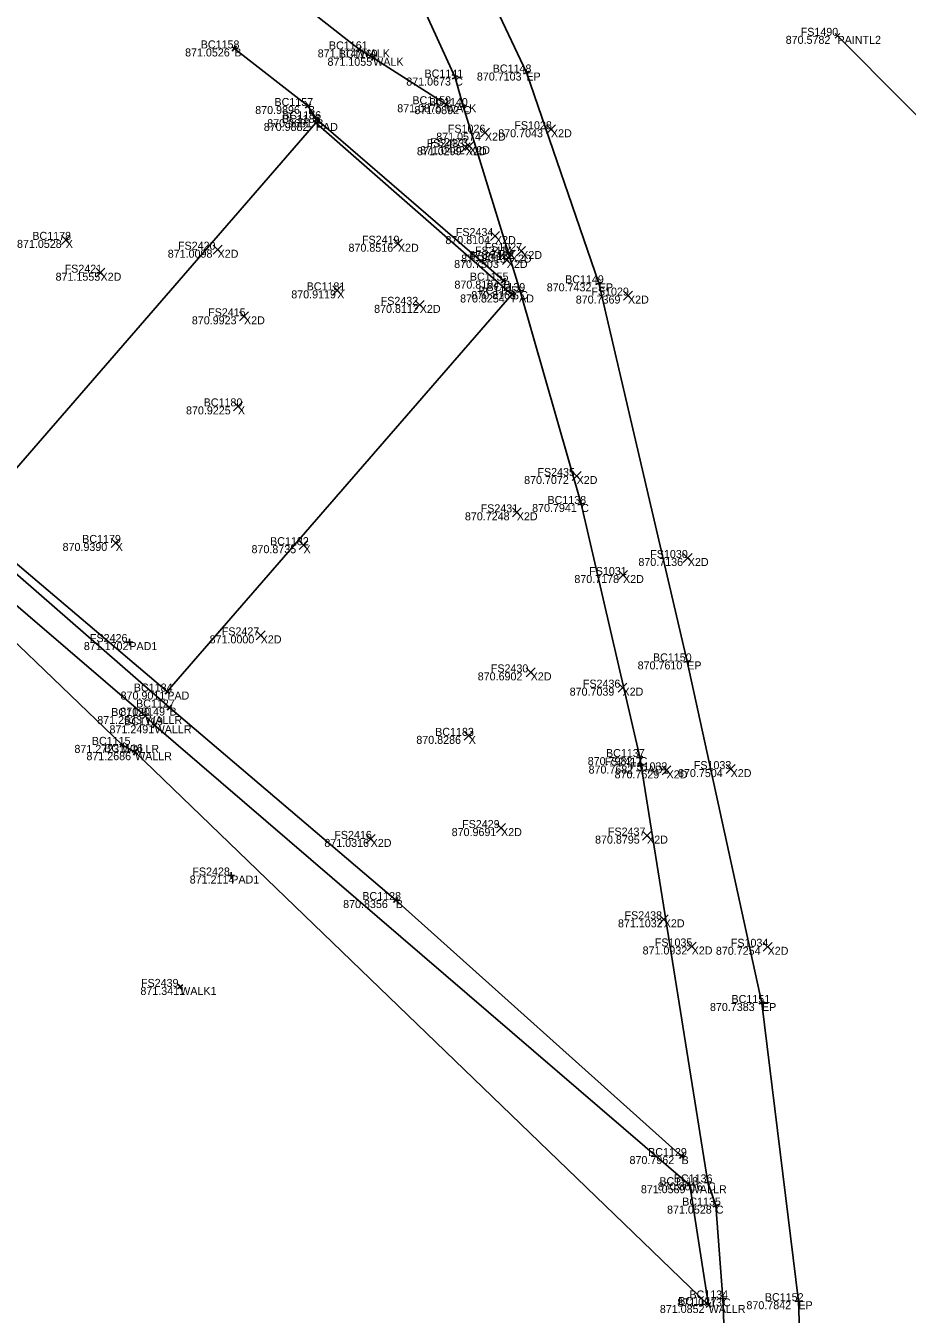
# Model space of a CAD drawing. Extents: x 1479425 to 1480294, y 379351 to 380102.
# Drawn here: x 1479567.93 to 1479574.53, y 379932.66 to 379942.32 of the extents above; entities that cross this region are included whole.
import ezdxf

# ---------------------------------------------------------------- set-up
doc = ezdxf.new("R2010")
doc.units = 0
for name, color, linetype in [('PM_X_Crosswalk', 7, 'Continuous'), ('PV_X_Curb', 7, 'Continuous'), ('PV_X_Walk', 7, 'Continuous'), ('RD_X_Concrete_Pad', 7, 'Continuous'), ('RD_X_Wall', 7, 'Continuous'), ('SV_X_Break_Lines', 7, 'Continuous'), ('SV_X_Random_Point', 7, 'Continuous'), ('SV_X_Shot_Marker', 7, 'Continuous'), ('SV_X_Text_Comment', 7, 'Continuous'), ('SV_X_Text_Elevation', 7, 'Continuous'), ('SV_X_Text_Name', 7, 'Continuous')]:
    doc.layers.add(name, color=color, linetype=linetype)

msp = doc.modelspace()

# ---------------------------------------------------------------- linework, layer by layer
at = {"layer": 'PM_X_Crosswalk'}
msp.add_lwpolyline([(1479636.371, 379879.5548), (1479574.01, 379942.241)], dxfattribs=at)
at = {"layer": 'PV_X_Curb'}
for points in [[(1479569.7374, 379946.0713), (1479571.6786, 379941.966), (1479572.2211, 379940.3862), (1479572.8837, 379937.5528), (1479573.4441, 379934.9926), (1479573.7165, 379932.7579), (1479573.8423, 379929.1036), (1479573.6746, 379925.8552), (1479573.045, 379921.8877), (1479571.771, 379917.2335), (1479569.497, 379912.1606), (1479567.166, 379908.6426), (1479563.944, 379905.002), (1479559.953, 379901.7586), (1479555.611, 379898.8117), (1479545.712, 379894.1043)], [(1479569.6747, 379945.147), (1479571.1449, 379941.9283), (1479571.2063, 379941.7143), (1479571.6328, 379940.3278), (1479572.0894, 379938.7326), (1479572.5276, 379936.8356), (1479573.0389, 379933.6479), (1479573.0983, 379933.4742), (1479573.1518, 379932.7783), (1479573.1584, 379932.5909), (1479573.2592, 379931.0122), (1479573.2781, 379927.5231), (1479573.155, 379925.8406), (1479572.586, 379922.1301), (1479571.403, 379917.5039), (1479569.157, 379912.5107), (1479566.948, 379909.0554), (1479563.851, 379905.5223), (1479559.694, 379902.1479), (1479555.354, 379899.3068), (1479545.42, 379894.5976)]]:
    msp.add_lwpolyline(points, dxfattribs=at)
at = {"layer": 'PV_X_Walk'}
msp.add_lwpolyline([(1479571.0763, 379941.7282), (1479570.531, 379942.0765), (1479570.4288, 379942.1393), (1479568.9868, 379943.271), (1479567.7208, 379944.1895), (1479567.6443, 379944.2666), (1479565.7789, 379946.1858), (1479564.4031, 379947.7838), (1479564.3033, 379947.845), (1479562.7309, 379949.5948), (1479560.4775, 379951.9792)], dxfattribs=at)
at = {"layer": 'RD_X_Concrete_Pad'}
msp.add_lwpolyline([(1479568.9885, 379937.3268), (1479571.5704, 379940.3025), (1479570.1014, 379941.5882), (1479567.4997, 379938.5893)], close=True, dxfattribs=at)
at = {"layer": 'RD_X_Wall'}
msp.add_lwpolyline([(1479564.6337, 379940.7266), (1479567.168, 379938.3359), (1479567.2924, 379938.2311), (1479568.6502, 379936.9271), (1479568.7466, 379936.8724), (1479573.0444, 379932.7293), (1479572.9032, 379933.627), (1479568.8936, 379937.0738), (1479568.8238, 379937.1435), (1479567.359, 379938.3988), (1479567.2981, 379938.4814), (1479564.6647, 379940.8093)], dxfattribs=at)
at = {"layer": 'SV_X_Break_Lines'}
for points in [[(1479571.5063, 379940.4064), (1479570.1057, 379941.6162), (1479570.0424, 379941.7153), (1479569.4905, 379942.1465)], [(1479564.6308, 379940.8576), (1479566.1289, 379939.6067), (1479567.3964, 379938.6081), (1479569.0046, 379937.2067), (1479570.7003, 379935.7642), (1479572.8418, 379933.8454)]]:
    msp.add_lwpolyline(points, dxfattribs=at)
at = {"layer": 'SV_X_Random_Point'}
for p, q in [((1479571.3347, 379941.482), (1479571.4013, 379941.5488)), ((1479571.3347, 379941.5488), (1479571.4013, 379941.482)), ((1479571.8297, 379941.5075), (1479571.8963, 379941.5743)), ((1479571.8297, 379941.5743), (1479571.8963, 379941.5075)), ((1479571.1917, 379941.3729), (1479571.2583, 379941.4397)), ((1479571.1917, 379941.4397), (1479571.2583, 379941.3729)), ((1479571.2167, 379941.3805), (1479571.2833, 379941.4473)), ((1479571.2167, 379941.4473), (1479571.2833, 379941.3805)), ((1479568.1945, 379940.6784), (1479568.2611, 379940.7452)), ((1479568.1945, 379940.7452), (1479568.2611, 379940.6784)), ((1479571.4097, 379940.7069), (1479571.4763, 379940.7737)), ((1479571.4097, 379940.7737), (1479571.4763, 379940.7069)), ((1479569.3317, 379940.6047), (1479569.3983, 379940.6715)), ((1479569.3317, 379940.6715), (1479569.3983, 379940.6047)), ((1479570.6827, 379940.6495), (1479570.7493, 379940.7163)), ((1479570.6827, 379940.7163), (1479570.7493, 379940.6495)), ((1479571.6067, 379940.5949), (1479571.6733, 379940.6617)), ((1479571.6067, 379940.6617), (1479571.6733, 379940.5949)), ((1479571.4987, 379940.5276), (1479571.5653, 379940.5944)), ((1479571.4987, 379940.5944), (1479571.5653, 379940.5276)), ((1479571.5287, 379940.568), (1479571.5953, 379940.6348)), ((1479571.5287, 379940.6348), (1479571.5953, 379940.568)), ((1479568.4547, 379940.4323), (1479568.5213, 379940.4991)), ((1479568.4547, 379940.4991), (1479568.5213, 379940.4323)), ((1479570.2279, 379940.3), (1479570.2945, 379940.3668)), ((1479570.2279, 379940.3668), (1479570.2945, 379940.3)), ((1479570.8467, 379940.1914), (1479570.9133, 379940.2582)), ((1479570.8467, 379940.2582), (1479570.9133, 379940.1914)), ((1479572.4067, 379940.2609), (1479572.4733, 379940.3277)), ((1479572.4067, 379940.3277), (1479572.4733, 379940.2609)), ((1479569.5297, 379940.1056), (1479569.5963, 379940.1724)), ((1479569.5297, 379940.1724), (1479569.5963, 379940.1056)), ((1479569.4841, 379939.4305), (1479569.5507, 379939.4973)), ((1479569.4841, 379939.4973), (1479569.5507, 379939.4305)), ((1479572.0217, 379938.9087), (1479572.0883, 379938.9755)), ((1479572.0217, 379938.9755), (1479572.0883, 379938.9087)), ((1479571.5737, 379938.6365), (1479571.6403, 379938.7033)), ((1479571.5737, 379938.7033), (1479571.6403, 379938.6365)), ((1479568.5682, 379938.4071), (1479568.6348, 379938.4739)), ((1479568.5682, 379938.4739), (1479568.6348, 379938.4071)), ((1479569.9758, 379938.3903), (1479570.0424, 379938.4571)), ((1479569.9758, 379938.4571), (1479570.0424, 379938.3903)), ((1479572.8547, 379938.2943), (1479572.9213, 379938.3611)), ((1479572.8547, 379938.3611), (1479572.9213, 379938.2943)), ((1479572.3697, 379938.1667), (1479572.4363, 379938.2335)), ((1479572.3697, 379938.2335), (1479572.4363, 379938.1667)), ((1479569.6547, 379937.7144), (1479569.7213, 379937.7812)), ((1479569.6547, 379937.7812), (1479569.7213, 379937.7144)), ((1479571.6777, 379937.437), (1479571.7443, 379937.5038)), ((1479571.6777, 379937.5038), (1479571.7443, 379937.437)), ((1479572.3657, 379937.3227), (1479572.4323, 379937.3895)), ((1479572.3657, 379937.3895), (1479572.4323, 379937.3227)), ((1479571.2134, 379936.9613), (1479571.28, 379937.0281)), ((1479571.2134, 379937.0281), (1479571.28, 379936.9613)), ((1479572.6957, 379936.7027), (1479572.7623, 379936.7695)), ((1479572.6957, 379936.7695), (1479572.7623, 379936.7027)), ((1479573.1757, 379936.7122), (1479573.2423, 379936.779)), ((1479573.1757, 379936.779), (1479573.2423, 379936.7122)), ((1479571.4557, 379936.2702), (1479571.5223, 379936.337)), ((1479571.4557, 379936.337), (1479571.5223, 379936.2702)), ((1479570.4787, 379936.189), (1479570.5453, 379936.2558)), ((1479570.4787, 379936.2558), (1479570.5453, 379936.189)), ((1479572.5497, 379936.2138), (1479572.6163, 379936.2806)), ((1479572.5497, 379936.2806), (1479572.6163, 379936.2138)), ((1479572.6747, 379935.5865), (1479572.7413, 379935.6533)), ((1479572.6747, 379935.6533), (1479572.7413, 379935.5865)), ((1479572.8837, 379935.383), (1479572.9503, 379935.4498)), ((1479572.8837, 379935.4498), (1479572.9503, 379935.383)), ((1479573.4527, 379935.3804), (1479573.5193, 379935.4472)), ((1479573.4527, 379935.4472), (1479573.5193, 379935.3804))]:
    msp.add_line(p, q, dxfattribs=at)
at = {"layer": 'SV_X_Shot_Marker'}
for p, q in [((1479573.9923, 379942.2234), (1479574.0277, 379942.2587)), ((1479574.0276, 379942.2233), (1479573.9924, 379942.2587)), ((1479574.01, 379942.241), (1479574.01, 379942.241)), ((1479569.5102, 379942.1311), (1479569.4708, 379942.1619)), ((1479569.4751, 379942.1268), (1479569.5059, 379942.1662)), ((1479569.4905, 379942.1465), (1479569.4905, 379942.1465)), ((1479570.4501, 379942.1262), (1479570.4075, 379942.1524)), ((1479570.4157, 379942.118), (1479570.4419, 379942.1606)), ((1479570.4288, 379942.1393), (1479570.4288, 379942.1393)), ((1479570.5175, 379942.0555), (1479570.5445, 379942.0976)), ((1479570.5521, 379942.0631), (1479570.5099, 379942.09)), ((1479570.531, 379942.0765), (1479570.531, 379942.0765)), ((1479571.1676, 379941.9387), (1479571.1222, 379941.9179)), ((1479571.1345, 379941.9511), (1479571.1553, 379941.9056)), ((1479571.1449, 379941.9283), (1479571.1449, 379941.9283)), ((1479571.7012, 379941.9767), (1479571.656, 379941.9553)), ((1479571.6679, 379941.9886), (1479571.6893, 379941.9434)), ((1479571.6786, 379941.966), (1479571.6786, 379941.966)), ((1479570.0213, 379941.7019), (1479570.0635, 379941.7288)), ((1479570.0559, 379941.6943), (1479570.0289, 379941.7364)), ((1479570.0424, 379941.7153), (1479570.0424, 379941.7153)), ((1479571.0974, 379941.7148), (1479571.0552, 379941.7417)), ((1479571.0628, 379941.7072), (1479571.0898, 379941.7493)), ((1479571.0763, 379941.7282), (1479571.0763, 379941.7282)), ((1479571.2303, 379941.7212), (1479571.1823, 379941.7074)), ((1479571.1994, 379941.7383), (1479571.2132, 379941.6903)), ((1479571.2063, 379941.7143), (1479571.2063, 379941.7143)), ((1479570.1246, 379941.5999), (1479570.0868, 379941.6326)), ((1479570.0894, 379941.5973), (1479570.122, 379941.6351)), ((1479570.1057, 379941.6162), (1479570.1057, 379941.6162)), ((1479570.1202, 379941.5718), (1479570.0826, 379941.6047)), ((1479570.0849, 379941.5694), (1479570.1179, 379941.607)), ((1479570.1014, 379941.5882), (1479570.1014, 379941.5882)), ((1479571.5252, 379940.3901), (1479571.4874, 379940.4228)), ((1479571.49, 379940.3875), (1479571.5226, 379940.4253)), ((1479571.5063, 379940.4064), (1479571.5063, 379940.4064)), ((1479572.2447, 379940.3943), (1479572.1975, 379940.3781)), ((1479572.213, 379940.4099), (1479572.2292, 379940.3626)), ((1479572.2211, 379940.3862), (1479572.2211, 379940.3862)), ((1479571.5515, 379940.3189), (1479571.5893, 379940.2861)), ((1479571.554, 379940.2836), (1479571.5868, 379940.3214)), ((1479571.5704, 379940.3025), (1479571.5704, 379940.3025)), ((1479571.6567, 379940.3352), (1479571.6089, 379940.3205)), ((1479571.6254, 379940.3517), (1479571.6401, 379940.3039)), ((1479571.6328, 379940.3278), (1479571.6328, 379940.3278)), ((1479572.1134, 379938.7395), (1479572.0654, 379938.7257)), ((1479572.0825, 379938.7567), (1479572.0963, 379938.7086)), ((1479572.0894, 379938.7326), (1479572.0894, 379938.7326)), ((1479568.679, 379937.6976), (1479568.729, 379937.6976)), ((1479568.704, 379937.7226), (1479568.704, 379937.6726)), ((1479568.704, 379937.6976), (1479568.704, 379937.6976)), ((1479572.908, 379937.5585), (1479572.8594, 379937.5471)), ((1479572.878, 379937.5772), (1479572.8894, 379937.5285)), ((1479572.8837, 379937.5528), (1479572.8837, 379937.5528)), ((1479568.9696, 379937.3432), (1479569.0074, 379937.3104)), ((1479568.9721, 379937.3079), (1479569.0049, 379937.3457)), ((1479568.9885, 379937.3268), (1479568.9885, 379937.3268)), ((1479568.9857, 379937.2231), (1479569.0234, 379937.1903)), ((1479569.021, 379937.2256), (1479568.9882, 379937.1879)), ((1479569.0046, 379937.2067), (1479569.0046, 379937.2067)), ((1479568.8061, 379937.1258), (1479568.8415, 379937.1612)), ((1479568.8415, 379937.1259), (1479568.8061, 379937.1612)), ((1479568.8238, 379937.1435), (1479568.8238, 379937.1435)), ((1479568.9126, 379937.0575), (1479568.8746, 379937.0901)), ((1479568.8773, 379937.0549), (1479568.9099, 379937.0928)), ((1479568.8936, 379937.0738), (1479568.8936, 379937.0738)), ((1479568.6322, 379936.9444), (1479568.6682, 379936.9098)), ((1479568.6675, 379936.9452), (1479568.6329, 379936.9091)), ((1479568.6502, 379936.9271), (1479568.6502, 379936.9271)), ((1479568.7249, 379936.8848), (1479568.7683, 379936.8601)), ((1479568.7589, 379936.8942), (1479568.7343, 379936.8507)), ((1479568.7466, 379936.8724), (1479568.7466, 379936.8724)), ((1479572.552, 379936.8412), (1479572.5032, 379936.83)), ((1479572.522, 379936.86), (1479572.5332, 379936.8113)), ((1479572.5274, 379936.7964), (1479572.5406, 379936.7482)), ((1479572.5276, 379936.8356), (1479572.5276, 379936.8356)), ((1479572.5099, 379936.7658), (1479572.5581, 379936.7789)), ((1479572.534, 379936.7723), (1479572.534, 379936.7723)), ((1479569.443, 379935.9481), (1479569.493, 379935.9481)), ((1479569.468, 379935.9731), (1479569.468, 379935.9231)), ((1479569.468, 379935.9481), (1479569.468, 379935.9481)), ((1479570.6813, 379935.7804), (1479570.7193, 379935.748)), ((1479570.7165, 379935.7833), (1479570.6841, 379935.7452)), ((1479570.7003, 379935.7642), (1479570.7003, 379935.7642)), ((1479569.0648, 379935.0984), (1479569.1052, 379935.1278)), ((1479569.0997, 379935.0929), (1479569.0703, 379935.1333)), ((1479569.085, 379935.1131), (1479569.085, 379935.1131)), ((1479573.4685, 379934.998), (1479573.4197, 379934.9873)), ((1479573.4388, 379935.017), (1479573.4494, 379934.9682)), ((1479573.4441, 379934.9926), (1479573.4441, 379934.9926)), ((1479572.8232, 379933.8621), (1479572.8604, 379933.8287)), ((1479572.8585, 379933.864), (1479572.8251, 379933.8268)), ((1479572.8418, 379933.8454), (1479572.8418, 379933.8454)), ((1479572.8785, 379933.6231), (1479572.9279, 379933.6309)), ((1479572.9071, 379933.6023), (1479572.8993, 379933.6517)), ((1479572.9032, 379933.627), (1479572.9032, 379933.627)), ((1479573.0636, 379933.6519), (1479573.0142, 379933.644)), ((1479573.0349, 379933.6726), (1479573.0429, 379933.6232)), ((1479573.0389, 379933.6479), (1479573.0389, 379933.6479)), ((1479573.0902, 379933.4979), (1479573.1064, 379933.4506)), ((1479573.122, 379933.4823), (1479573.0746, 379933.4661)), ((1479573.0983, 379933.4742), (1479573.0983, 379933.4742)), ((1479573.0264, 379932.7467), (1479573.0624, 379932.712)), ((1479573.0617, 379932.7473), (1479573.027, 379932.7113)), ((1479573.0444, 379932.7293), (1479573.0444, 379932.7293)), ((1479573.1767, 379932.7802), (1479573.1269, 379932.7764)), ((1479573.1499, 379932.8032), (1479573.1537, 379932.7534)), ((1479573.1518, 379932.7783), (1479573.1518, 379932.7783)), ((1479573.7413, 379932.7609), (1479573.6917, 379932.7549)), ((1479573.7135, 379932.7827), (1479573.7195, 379932.7331)), ((1479573.7165, 379932.7579), (1479573.7165, 379932.7579))]:
    msp.add_line(p, q, dxfattribs=at)

# ---------------------------------------------------------------- texts
at = {"layer": 'SV_X_Text_Comment'}
for s, p in [('PAINTL2', (1479574.01, 379942.181)), ('B', (1479569.4905, 379942.0865)), ('WALK', (1479570.4288, 379942.0793)), ('WALK', (1479570.531, 379942.0165)), ('C', (1479571.1449, 379941.8683)), ('EP', (1479571.6786, 379941.906)), ('B', (1479570.0424, 379941.6553)), ('WALK', (1479571.0763, 379941.6682)), ('C', (1479571.2063, 379941.6543)), ('B', (1479570.1057, 379941.5562)), ('PAD', (1479570.1014, 379941.5282)), ('X2D', (1479571.368, 379941.4554)), ('X2D', (1479571.863, 379941.4809)), ('X2D', (1479571.225, 379941.3463)), ('X2D', (1479571.25, 379941.3539)), ('X2D', (1479571.443, 379940.6803)), ('X', (1479568.2278, 379940.6518)), ('X2D', (1479570.716, 379940.6229)), ('X2D', (1479569.365, 379940.5781)), ('X2D', (1479571.532, 379940.501)), ('X2D', (1479571.562, 379940.5414)), ('X2D', (1479571.64, 379940.5683)), ('X2D', (1479568.488, 379940.4057)), ('B', (1479571.5063, 379940.3464)), ('EP', (1479572.2211, 379940.3262)), ('X', (1479570.2612, 379940.2734)), ('PAD', (1479571.5704, 379940.2425)), ('C', (1479571.6328, 379940.2678)), ('X2D', (1479572.44, 379940.2343)), ('X2D', (1479570.88, 379940.1648)), ('X2D', (1479569.563, 379940.079)), ('X', (1479569.5174, 379939.4039)), ('X2D', (1479572.055, 379938.8821)), ('C', (1479572.0894, 379938.6726)), ('X2D', (1479571.607, 379938.6099)), ('X', (1479568.6015, 379938.3805)), ('X', (1479570.0091, 379938.3637)), ('X2D', (1479572.888, 379938.2677)), ('X2D', (1479572.403, 379938.1401)), ('X2D', (1479569.688, 379937.6878)), ('PAD1', (1479568.704, 379937.6376)), ('EP', (1479572.8837, 379937.4928)), ('X2D', (1479571.711, 379937.4104)), ('PAD', (1479568.9885, 379937.2668)), ('X2D', (1479572.399, 379937.2961)), ('B', (1479569.0046, 379937.1467)), ('WALLR', (1479568.8238, 379937.0835)), ('WALLR', (1479568.8936, 379937.0138)), ('X', (1479571.2467, 379936.9347)), ('WALLR', (1479568.6502, 379936.8671)), ('WALLR', (1479568.7466, 379936.8124)), ('C', (1479572.5276, 379936.7756)), ('PAD1', (1479572.534, 379936.7123)), ('X2D', (1479572.729, 379936.6761)), ('X2D', (1479573.209, 379936.6856)), ('X2D', (1479571.489, 379936.2436)), ('X2D', (1479570.512, 379936.1624)), ('X2D', (1479572.583, 379936.1872)), ('PAD1', (1479569.468, 379935.8881)), ('B', (1479570.7003, 379935.7042)), ('X2D', (1479572.708, 379935.5599)), ('X2D', (1479572.917, 379935.3564)), ('X2D', (1479573.486, 379935.3538)), ('WALK1', (1479569.085, 379935.0531)), ('EP', (1479573.4441, 379934.9326)), ('B', (1479572.8418, 379933.7854)), ('WALLR', (1479572.9032, 379933.567)), ('C', (1479573.0389, 379933.5879)), ('C', (1479573.0983, 379933.4142)), ('WALLR', (1479573.0444, 379932.6693)), ('C', (1479573.1518, 379932.7183)), ('EP', (1479573.7165, 379932.6979))]:
    msp.add_text(s, height=0.06, dxfattribs=at).set_placement(p)
at = {"layer": 'SV_X_Text_Elevation'}
for s, p in [('870.5782', (1479573.6217, 379942.181)), ('871.0526', (1479569.1216, 379942.0865)), ('871.1147', (1479570.1152, 379942.0793)), ('871.1055', (1479570.1886, 379942.0165)), ('871.0673', (1479570.7788, 379941.8683)), ('870.7103', (1479571.3078, 379941.906)), ('870.9896', (1479569.647, 379941.6553)), ('871.0875', (1479570.7112, 379941.6682)), ('871.0892', (1479570.8397, 379941.6543)), ('870.9681', (1479569.7366, 379941.5562)), ('870.9882', (1479569.7112, 379941.5282)), ('871.0574', (1479571.0033, 379941.4554)), ('870.7043', (1479571.4681, 379941.4809)), ('871.0299', (1479570.8584, 379941.3463)), ('871.0432', (1479570.883, 379941.3539)), ('870.8104', (1479571.0717, 379940.6803)), ('871.0528', (1479567.8622, 379940.6518)), ('870.8516', (1479570.3461, 379940.6229)), ('871.0098', (1479568.9918, 379940.5781)), ('870.7503', (1479571.1375, 379940.501)), ('870.8013', (1479571.1902, 379940.5414)), ('870.7422', (1479571.2521, 379940.5683)), ('871.1555', (1479568.1512, 379940.4057)), ('870.8194', (1479571.1397, 379940.3464)), ('870.7432', (1479571.8314, 379940.3262)), ('870.9119', (1479569.9173, 379940.2734)), ('870.8254', (1479571.1821, 379940.2425)), ('870.8163', (1479571.2658, 379940.2678)), ('870.7369', (1479572.0488, 379940.2343)), ('870.8112', (1479570.538, 379940.1648)), ('870.9923', (1479569.1723, 379940.079)), ('870.9225', (1479569.1286, 379939.4039)), ('870.7072', (1479571.6619, 379938.8821)), ('870.7941', (1479571.7218, 379938.6726)), ('870.7248', (1479571.2182, 379938.6099)), ('870.9390', (1479568.2037, 379938.3805)), ('870.8735', (1479569.6194, 379938.3637)), ('870.7136', (1479572.5181, 379938.2677)), ('870.7178', (1479572.0383, 379938.1401)), ('871.0000', (1479569.3054, 379937.6878)), ('871.1702', (1479568.363, 379937.6376)), ('870.7610', (1479572.5124, 379937.4928)), ('870.6902', (1479571.3142, 379937.4104)), ('870.9011', (1479568.6384, 379937.2668)), ('870.7039', (1479572.0031, 379937.2961)), ('870.9149', (1479568.6366, 379937.1467)), ('871.2533', (1479568.4634, 379937.0835)), ('871.2491', (1479568.5553, 379937.0138)), ('870.8286', (1479570.8541, 379936.9347)), ('871.2723', (1479568.2926, 379936.8671)), ('871.2686', (1479568.3824, 379936.8124)), ('870.7982', (1479572.1383, 379936.7756)), ('870.7682', (1479572.1447, 379936.7123)), ('870.7629', (1479572.3397, 379936.6761)), ('870.7504', (1479572.815, 379936.6856)), ('870.9691', (1479571.119, 379936.2436)), ('871.0316', (1479570.1648, 379936.1624)), ('870.8795', (1479572.1933, 379936.1872)), ('871.2114', (1479569.1563, 379935.8881)), ('870.8356', (1479570.3058, 379935.7042)), ('871.1032', (1479572.3651, 379935.5599)), ('871.0932', (1479572.5495, 379935.3564)), ('870.7254', (1479573.0986, 379935.3538)), ('871.3411', (1479568.7868, 379935.0531)), ('870.7383', (1479573.0544, 379934.9326)), ('870.7962', (1479572.4516, 379933.7854)), ('871.0589', (1479572.5366, 379933.567)), ('870.8016', (1479572.6634, 379933.5879)), ('871.0528', (1479572.7327, 379933.4142)), ('871.0852', (1479572.6788, 379932.6693)), ('871.0813', (1479572.8094, 379932.7183)), ('870.7842', (1479573.3277, 379932.6979))]:
    msp.add_text(s, height=0.06, dxfattribs=at).set_placement(p)
at = {"layer": 'SV_X_Text_Name'}
for s, p in [('FS1490', (1479573.7341, 379942.241)), ('BC1158', (1479569.2388, 379942.1465)), ('BC1161', (1479570.1992, 379942.1393)), ('BC1160', (1479570.2736, 379942.0765)), ('BC1148', (1479571.4264, 379941.966)), ('BC1141', (1479570.9157, 379941.9283)), ('BC1157', (1479569.7911, 379941.7153)), ('BC1159', (1479570.8246, 379941.7282)), ('BC1140', (1479570.9494, 379941.7143)), ('BC1186', (1479569.8464, 379941.5882)), ('BC1156', (1479569.8507, 379941.6162)), ('FS1026', (1479571.0903, 379941.5154)), ('FS1028', (1479571.5886, 379941.5409)), ('FS2433', (1479570.9316, 379941.4063)), ('FS2473', (1479570.9585, 379941.4139)), ('BC1178', (1479567.977, 379940.7118)), ('FS2419', (1479570.4468, 379940.6829)), ('FS2434', (1479571.1501, 379940.7403)), ('FS2420', (1479569.0683, 379940.6381)), ('FS2414', (1479571.2937, 379940.6014)), ('FS1027', (1479571.366, 379940.6283)), ('FS2418', (1479571.2628, 379940.561)), ('FS2421', (1479568.2191, 379940.4657)), ('BC1155', (1479571.255, 379940.4064)), ('BC1181', (1479570.0325, 379940.3334)), ('BC1185', (1479571.3191, 379940.3025)), ('BC1139', (1479571.3801, 379940.3278)), ('BC1149', (1479571.9689, 379940.3862)), ('FS1029', (1479572.1656, 379940.2943)), ('FS2432', (1479570.5871, 379940.2248)), ('FS2415', (1479569.2942, 379940.139)), ('BC1180', (1479569.2609, 379939.4639)), ('FS2435', (1479571.7616, 379938.9421)), ('FS2431', (1479571.3362, 379938.6699)), ('BC1138', (1479571.8367, 379938.7326)), ('BC1179', (1479568.3507, 379938.4405)), ('BC1182', (1479569.7583, 379938.4237)), ('FS1030', (1479572.6069, 379938.3277)), ('FS1031', (1479572.1497, 379938.2001)), ('FS2426', (1479568.4087, 379937.6976)), ('FS2427', (1479569.3965, 379937.7478)), ('BC1150', (1479572.6272, 379937.5528)), ('FS2430', (1479571.4124, 379937.4704)), ('BC1184', (1479568.7377, 379937.3268)), ('FS2436', (1479572.1019, 379937.3561)), ('BC1127', (1479568.7543, 379937.2067)), ('BC1120', (1479568.5683, 379937.1435)), ('BC1119', (1479568.6655, 379937.0738)), ('BC1115', (1479568.4226, 379936.9271)), ('BC1183', (1479570.9954, 379936.9947)), ('BC1116', (1479568.5152, 379936.8724)), ('BC1137', (1479572.2754, 379936.8356)), ('FS2417', (1479572.2652, 379936.7723)), ('FS1032', (1479572.4536, 379936.7361)), ('FS1033', (1479572.9331, 379936.7456)), ('FS2429', (1479571.1971, 379936.3036)), ('FS2437', (1479572.2896, 379936.2472)), ('FS2416', (1479570.2395, 379936.2224)), ('FS2428', (1479569.1761, 379935.9481)), ('BC1128', (1479570.4495, 379935.7642)), ('FS2438', (1479572.4142, 379935.6199)), ('FS1035', (1479572.6411, 379935.4164)), ('FS1034', (1479573.2106, 379935.4138)), ('FS2439', (1479568.7912, 379935.1131)), ('BC1151', (1479573.2154, 379934.9926)), ('BC1129', (1479572.591, 379933.8454)), ('BC1136', (1479572.7829, 379933.6479)), ('BC1118', (1479572.6751, 379933.627)), ('BC1135', (1479572.8461, 379933.4742)), ('BC1134', (1479572.9001, 379932.7783)), ('BC1117', (1479572.8168, 379932.7293)), ('BC1152', (1479573.4657, 379932.7579))]:
    msp.add_text(s, height=0.06, dxfattribs=at).set_placement(p)

doc.saveas('drawing.dxf')
